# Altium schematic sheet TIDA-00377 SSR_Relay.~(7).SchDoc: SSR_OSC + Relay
size 431 x 279 mm; Date: Not shown in title block; ApprovedBy: Not shown in title block; CheckedBy: Not shown in title block; Author: Not shown in title block; CompanyName: Not shown in title block; DrawnBy: Jarrod Krebs; Engineer: Not shown in title block; Organization: Not shown in title block; Address1: Not shown in title block; Address2: Not shown in title block; Address3: Not shown in title block; Address4: Not shown in title block; DocumentNumber: 1; Revision: Use project parameter SCH_Rev; SheetNumber: 2; SheetTotal: 3; PageSetup: Record=PageOptions¦CenterHorizontal=True¦CenterVertical=True¦PrintScale=0.62¦XCorrection=1.00¦YCorrection=1.00¦PrintKind=0¦BorderSize=5000000¦LeftOffset=0¦BottomOffset=0¦Orientation=2¦PaperLength=1000¦PaperWidth=1000¦Scale=100¦PaperSource=15¦PrintQuality=-3¦MediaType=1¦DitherType=10¦PrintScaleMode=1¦PaperKind=Letter¦PaperIndex=1
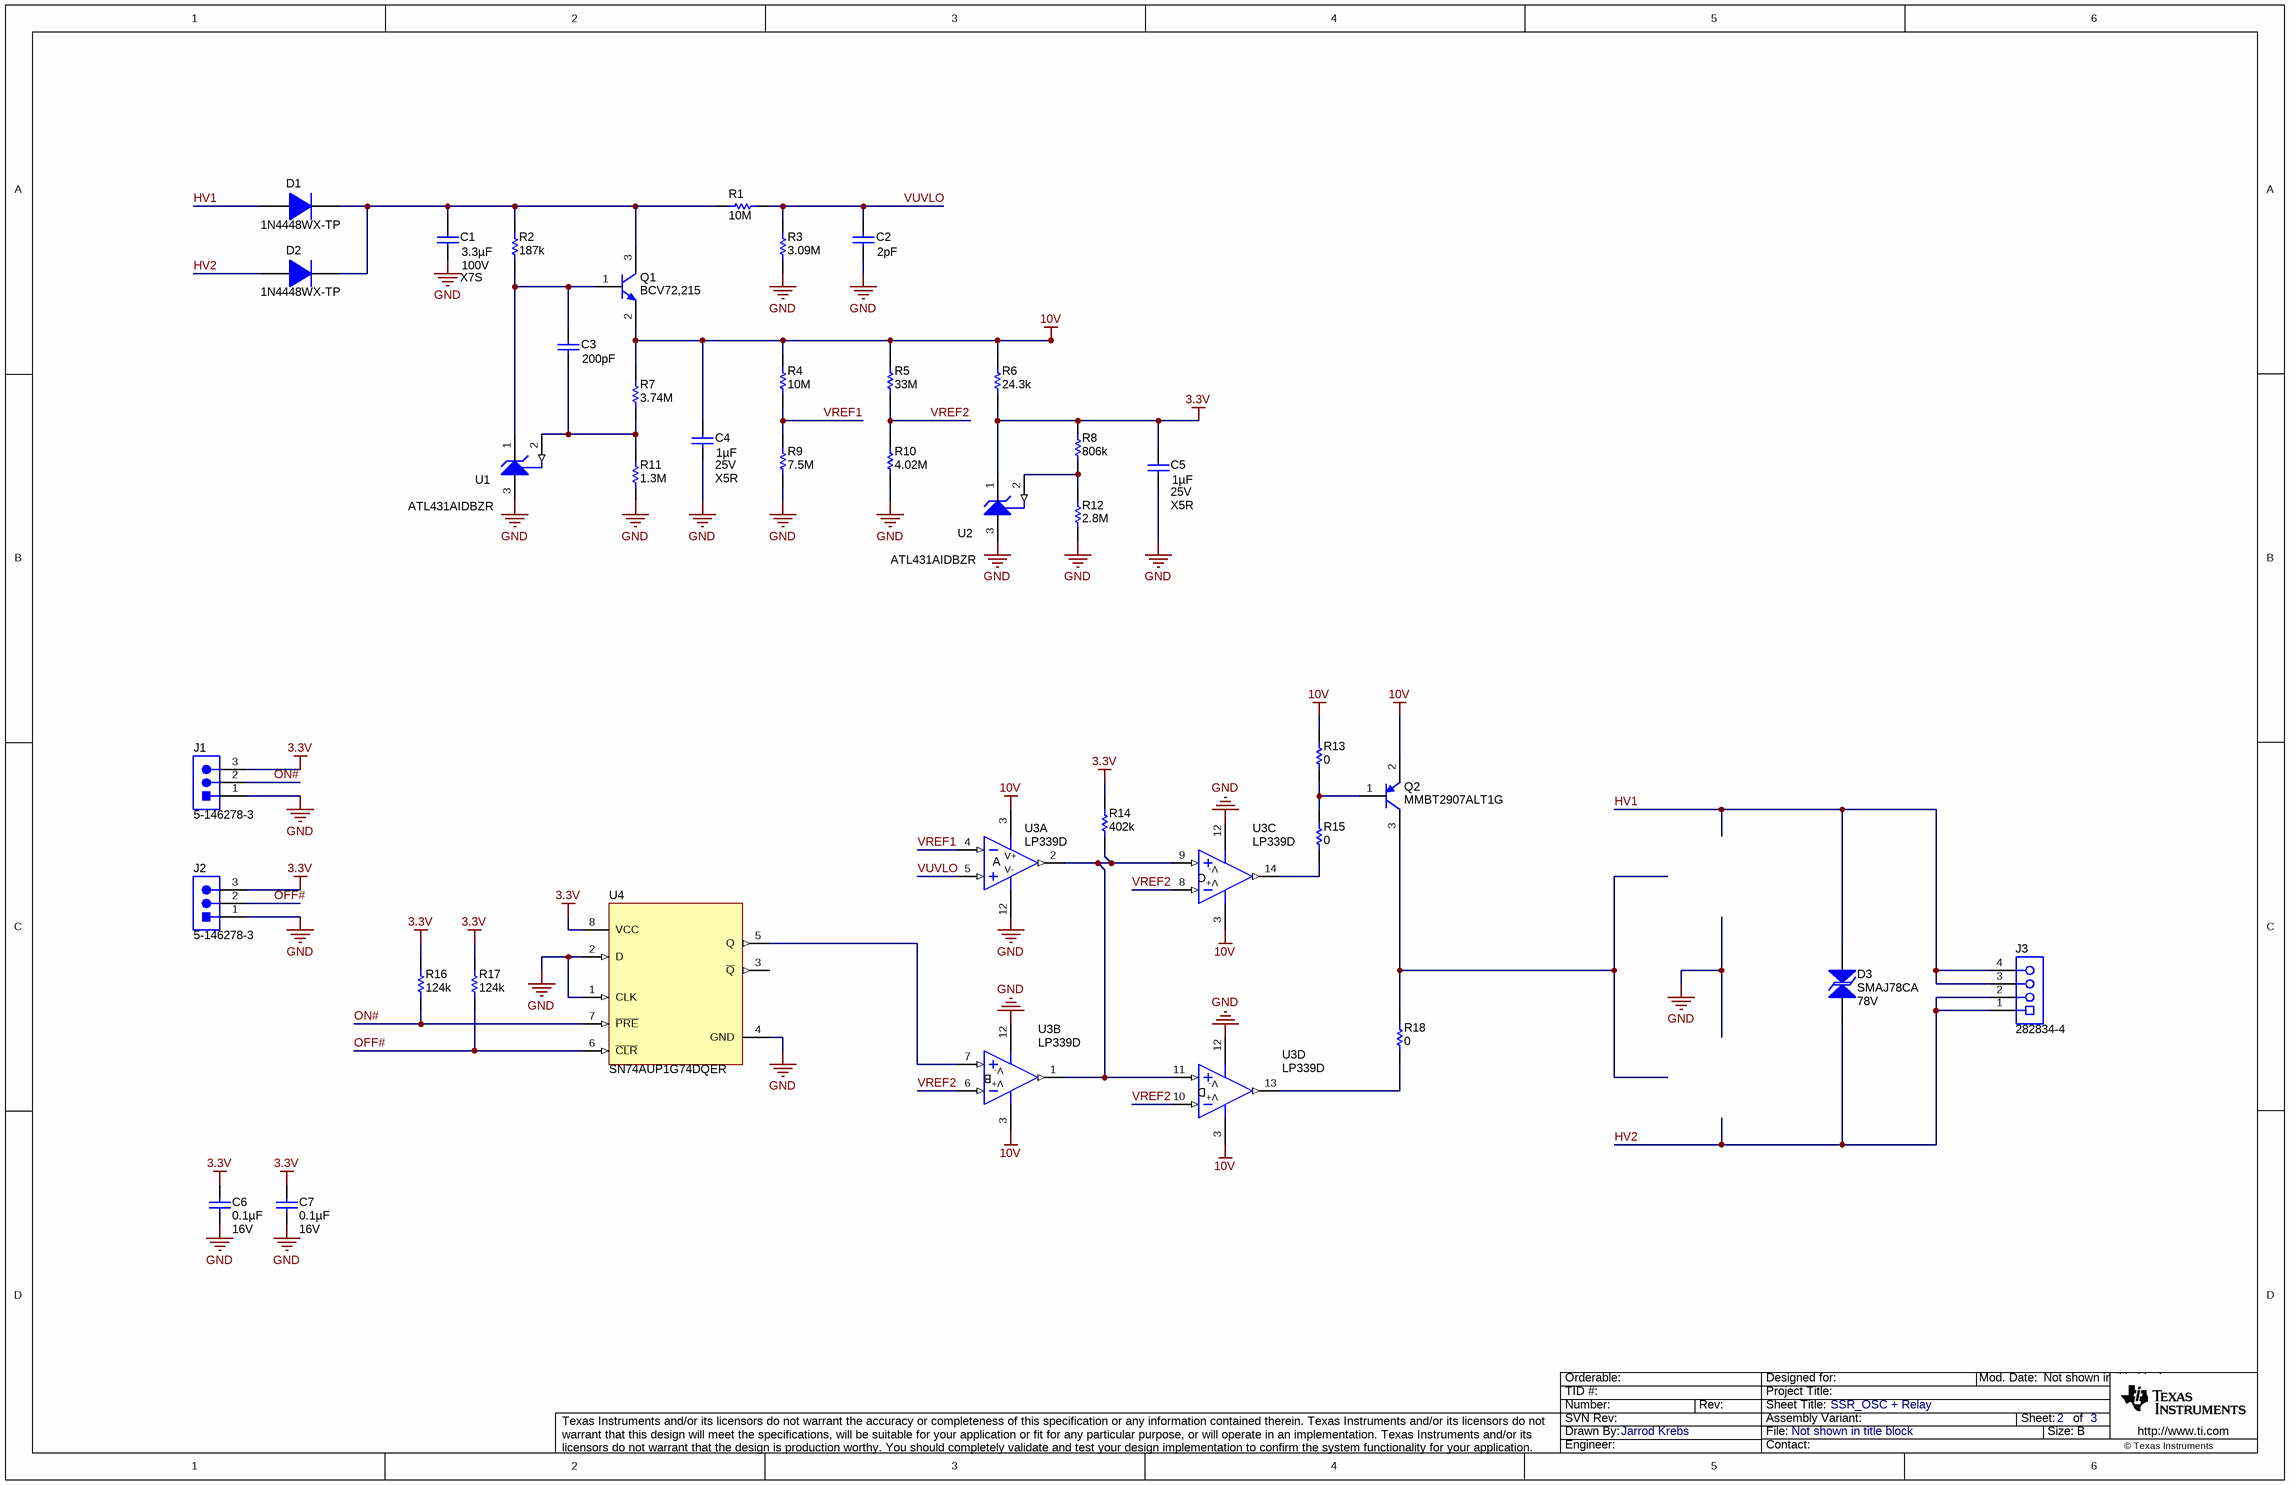
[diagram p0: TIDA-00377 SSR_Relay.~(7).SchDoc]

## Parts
C1  ValueDisplayed: 3.3µF  VDC_V: 100V  TempCo: X7S  [0603]  (hidden comment: GRM188R61E105KA12D)
C2  ValueDisplayed: 2pF  [0603]  (hidden comment: GRM188R61E105KA12D)
C3  ValueDisplayed: 200pF  [0603]  (hidden comment: GRM188R61E105KA12D)
C4  ValueDisplayed: 1µF  Value2: 25V  TempCo: X5R  [0603]  (hidden comment: GRM188R61E105KA12D)
C5  ValueDisplayed: 1µF  Value2: 25V  TempCo: X5R  [0603]  (hidden comment: GRM188R61E105KA12D)
C6  ValueDisplayed: 0.1µF  Value2: 16V  [0603]  (hidden comment: GRM188R71C104KA01D)
C7  ValueDisplayed: 0.1µF  Value2: 16V  [0603]  (hidden comment: GRM188R71C104KA01D)
D1  1N4448WX-TP  [sod-323]
D2  1N4448WX-TP  [sod-323]
D3  SMAJ78CA  value 78V  [SMA]
J1  5-146278-3  [TE_5-146278-3]
J2  5-146278-3  [TE_5-146278-3]
J3  282834-4  [TEC_282834-4]
Q1  BCV72,215  [SOT-23]
Q2  MMBT2907ALT1G  [SOT-23]
R1  ValueDisplayed: 10M  [0805_HV]  (hidden comment: CRCW08050000Z0EA)
R2  ValueDisplayed: 187k  [0805_HV]  (hidden comment: CRCW08050000Z0EA)
R3  ValueDisplayed: 3.09M  [0805_HV]  (hidden comment: CRCW08050000Z0EA)
R4  ValueDisplayed: 10M  [0805_HV]  (hidden comment: CRCW08050000Z0EA)
R5  ValueDisplayed: 33M  [0805_HV]  (hidden comment: CRCW08050000Z0EA)
R6  ValueDisplayed: 24.3k  [0805_HV]  (hidden comment: CRCW08050000Z0EA)
R7  ValueDisplayed: 3.74M  [0805_HV]  (hidden comment: CRCW08050000Z0EA)
R8  ValueDisplayed: 806k  [0805_HV]  (hidden comment: CRCW08050000Z0EA)
R9  ValueDisplayed: 7.5M  [0805_HV]  (hidden comment: CRCW08050000Z0EA)
R10  ValueDisplayed: 4.02M  [0805_HV]  (hidden comment: CRCW08050000Z0EA)
R11  ValueDisplayed: 1.3M  [0805_HV]  (hidden comment: CRCW08050000Z0EA)
R12  ValueDisplayed: 2.8M  [0805_HV]  (hidden comment: CRCW08050000Z0EA)
R13  ValueDisplayed: 0  [0805_HV]  (hidden comment: CRCW08050000Z0EA)
R14  ValueDisplayed: 402k  [0805_HV]  (hidden comment: CRCW08050000Z0EA)
R15  ValueDisplayed: 0  [0805_HV]  (hidden comment: CRCW08050000Z0EA)
R16  ValueDisplayed: 124k  [0402]  (hidden comment: CRCW0402100KJNED)
R17  ValueDisplayed: 124k  [0402]  (hidden comment: CRCW0402100KJNED)
R18  ValueDisplayed: 0  [0805_HV]  (hidden comment: CRCW08050000Z0EA)
U1  ATL431AIDBZR  [DBZ0003A_M]
U2  ATL431AIDBZR  [DBZ0003A_M]
U3  LP339D  [D0014A_N]  (parts A,B,C,D of 4)
U4  SN74AUP1G74DQER  [DQE0008A]

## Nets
3.3V: C5.2 C6.2 C7.2 J1.3 J2.3 R6.2 R8.1 R14.1 R16.2 R17.2 U2.1(CATHODE) U4.8(VCC)
10V: C4.2 Q1.2(E) Q2.2(E) R4.1 R5.1 R6.1 R7.1 R13.1 U3.3(V+)
GND: C1.1 C2.1 C4.1 C5.1 C6.1 C7.1 J1.1 J2.1 R3.2 R9.2 R10.2 R11.2 R12.2 U1.3(ANODE) U2.3(ANODE) U3.12(V-) U4.1(CLK) U4.2(D) U4.4(GND)
HV1: D1.2(A) D3.2 J3.3 J3.4
HV2: D2.2(A) D3.1 J3.1 J3.2
OFF#: J2.2 R17.1 U4.6(~{CLR})
ON#: J1.2 R16.1 U4.7(~{PRE})
VREF1: R4.2 R9.1 U3.4(-IN1)
VREF2: R5.2 R10.1 U3.6(-IN2) U3.8(-IN3) U3.10(-IN4)
VUVLO: C2.2 R1.2 R3.1 U3.5(+IN1)
NetC1_2: C1.2 D1.1(K) D2.1(K) Q1.3(C) R1.1 R2.1
NetC3_1: C3.1 R7.2 R11.1 U1.2(REF)
NetC3_2: C3.2 Q1.1(B) R2.2 U1.1(CATHODE)
NetQ2_1: Q2.1(B) R13.2 R15.1
NetQ2_3: Q2.3(C) R18.2
NetR8_2: R8.2 R12.1 U2.2(REF)
NetR14_2: R14.2 U3.1(OUT2) U3.2(OUT1) U3.9(+IN3) U3.11(+IN4)
NetR15_2: R15.2 U3.14(OUT3)
NetR18_1: R18.1 U3.13(OUT4)
NetU3_7: U3.7(+IN2) U4.5(Q)

Not connected (* = marked no-connect by the designer): U4 3(~{Q})

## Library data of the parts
C1 = GRM188R61E105KA12D: CAP, CERM, 3.3 µF, 100 V, +/- 10%, X5R, 0603; Manufacturer: MuRata; Polarized: N; CompType: Capacitor; Value: 1uF; U/M: EA; Cap_F: 0.000001; Tolerance_%: 10; Value1: Unknown; TaMin_C: -55; TaMax_C: 85; AEC Category: Q200
C2 C3 = GRM188R61E105KA12D: CAP, CERM, 1 µF, 25 V, +/- 10%, X5R, 0603; Manufacturer: MuRata; Polarized: N; CompType: Capacitor; Value: 1uF; U/M: EA; Cap_F: 0.000001; Tolerance_%: 10; Value1: Unknown; VDC_V: 25; Value2: 25V; TaMin_C: -55; TaMax_C: 85; AEC Category: Q200
C4 C5 = GRM188R61E105KA12D: CAP, CERM, 1 µF, 25 V, +/- 10%, X5R, 0603; Manufacturer: MuRata; Polarized: N; CompType: Capacitor; Value: 1uF; U/M: EA; Cap_F: 0.000001; Tolerance_%: 10; Value1: Unknown; VDC_V: 25; TaMin_C: -55; TaMax_C: 85; AEC Category: Q200
C6 C7 = GRM188R71C104KA01D: CAP, CERM, 0.1 µF, 16 V, +/- 10%, X7R, 0603; Manufacturer: MuRata; Polarized: N; CompType: Capacitor; Value: 0.1uF; U/M: EA; Cap_F: 0.0000001; Tolerance_%: 10; Value1: Unknown; VDC_V: 16; TaMin_C: -55; TaMax_C: 125; AEC Category: Q200
D1 D2 = 1N4448WX-TP: Diode, Switching, 75 V, 0.25 A, SOD-323; Manufacturer: Micro Commercial Components; U/M: EA; Value: 75V; Value1: 0.25A; Io_A: 0.25; Vr_V: 75; TJmax_C: 150; AEC Category: Q101
D3 = SMAJ78CA: Diode, TVS, Bi, 78 V, 400 W, SMA; Manufacturer: Littelfuse; U/M: EA; Power_W: 400; Vr_V: 78; Value1: 400W; RJA_CperW: 120; AEC Category: Q101
J1 J2 = 5-146278-3: Header, 100mil, 3x1, Tin, TH; Manufacturer: TE Connectivity; SymbolCreator: a0799628
J3 = 282834-4: Terminal Block, 100mil, 4X1 TH; Manufacturer: TE Connectivity; SymbolCreator: a0411947
Q1 = PBSS4160T, NXP Semiconductor: Transistor, NPN, 60 V, 0.9 A, SOT-23; CompType: BJT; PNP: 0; NPN: 1; Vceo_V: 60; Vcesat1_V: 0.25; Value: 60 V; IcRated_A: 0.1; Value1: 0.1 A; TaMin_C: -65; TaMax_C: 150; U/M: EA; AEC Category: Q101
Q2 = MMBT2907ALT1G, ON Semiconductor: Transistor, PNP, 60 V, 0.6 A, SOT-23; CompType: BJT; PNP: 1; NPN: 0; Vceo_V: 60; Vcesat1_V: 1.6; Value: 60 V; IcRated_A: 0.6; Value1: 0.6 A; TaMin_C: -55; TaMax_C: 150; U/M: EA; AEC Category: Q101
R1-R15 R18 = CRCW08050000Z0EA: RES, 0, 5%, 0.125 W, 0805; Manufacturer: Vishay-Dale; CompType: Resistor; Value: 0; Value_Code: 0000; Tolerance_%: 5; Power_W: 0.125; Value2: 0.125W; VDC_V: 150; TempCo: 200 ppm/C; EIA_Code: E24; U/M: EA; AEC Category: Q200
R16 R17 = CRCW0402100KJNED: RES, 100 k, 5%, 0.063 W, 0402; Manufacturer: Vishay-Dale; CompType: Resistor; Value: 100k; Res_ohm: 100000; Tolerance_%: 5; Power_W: 0.063; Value2: 0.063W; VDC_V: 50; TempCo: 200 ppm/C; EIA_Code: E24; U/M: EA; AEC Category: Q200
U1 U2 = ATL431AIDBZR: 2.5V Low Iq Adjustable Precision Shunt Regulator, DBZ0003A; Manufacturer: Texas Instruments; SymbolCreator: a0412235; CompType: IC; U/M: EA
U3 = LP339D: Quad, Low-Power, General Purpose Differential Comparator, D0014A; Manufacturer: Texas Instruments; SymbolCreator: Altium; CompType: OpAmp IC
U4 = SN74AUP1G74DQER: LOW-POWER SINGLE POSITIVE-EDGE-TRIGGERED D-TYPE FLIP-FLOP WITH CLEAR AND PRESET, DQE0008A; Manufacturer: Texas Instruments; SymbolCreator: a0799628; CompType: IC; U/M: EA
